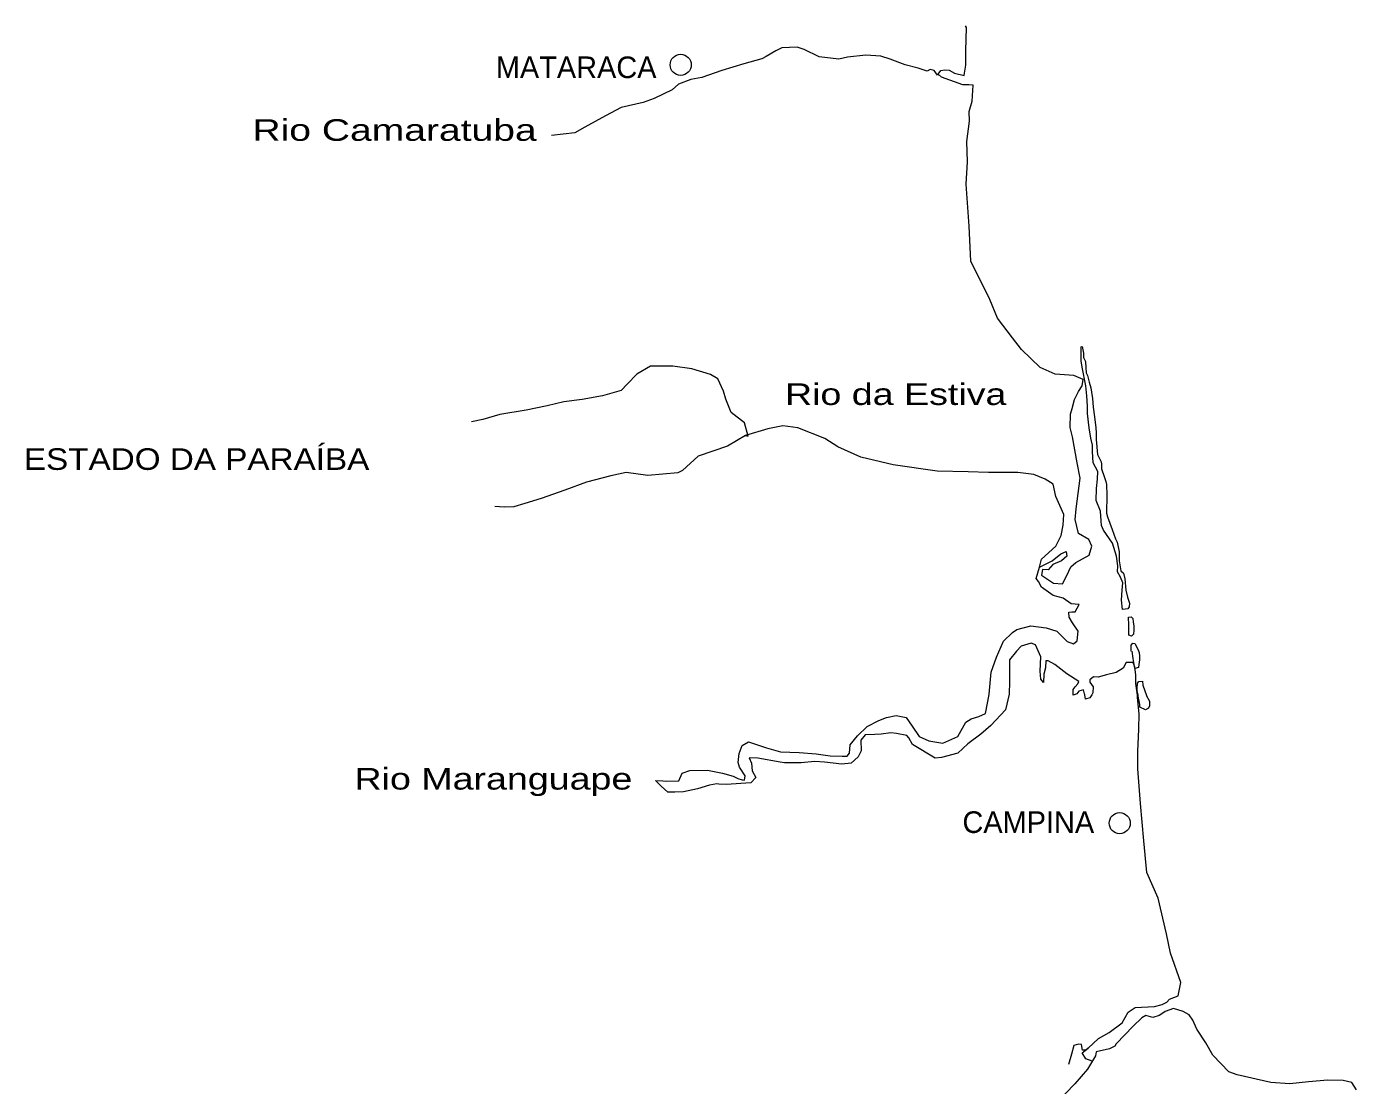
# Model space of a CAD drawing. Extents: x 47169 to 972804, y 7447977 to 9608469.
# Drawn here: x 916706 to 958528, y 9236610 to 9269921 of the extents above; entities that cross this region are included whole.
import ezdxf
from ezdxf.enums import TextEntityAlignment as Align

# ---------------------------------------------------------------- set-up
doc = ezdxf.new("R2010")
doc.units = 0
doc.header["$LTSCALE"] = 270
doc.layers.add('1', color=7, linetype='Continuous', lineweight=13)
doc.layers.add('2', color=7, linetype='Continuous', lineweight=13)
doc.layers.add('3', color=7, linetype='Continuous')

msp = doc.modelspace()

# ---------------------------------------------------------------- linework, layer by layer
at = {"layer": '1'}
for points in [[(949750.6, 9256201.2), (949604.4, 9257017), (949529.3, 9257306.9), (949536.1, 9257725.8), (949587.4, 9257901.5), (949664, 9258190.2), (949788, 9258438.5), (949902.5, 9258621.5), (949930.8, 9258821.9), (949644.8, 9258947.3), (949053.4, 9258987.6), (948577.6, 9259195.5), (947994.9, 9259760), (947713.2, 9260133.5), (947244, 9260744.7), (946997.3, 9261335.2), (946402.2, 9262542.5), (946349.1, 9263637.9), (946251.3, 9264966.3), (946294.7, 9265666.4), (946281, 9266301.5), (946356, 9266944.8), (946345.2, 9267250.7), (946446.5, 9267571.3), (946478.3, 9268077.5), (946335.4, 9268087.5), (946214.6, 9268089.6), (946151.5, 9268090.1), (945475.2, 9268332.8), (945372.9, 9268423.4), (945462.4, 9268534.6), (945575.7, 9268564.7), (945718.6, 9268554.7), (945892.9, 9268455.7), (946188.2, 9268386.8), (946205.4, 9268459.8), (946249.6, 9268707.7), (946248.8, 9269158.8), (946261.4, 9269891.2), (946229.6, 9269939.1)], [(945372.9, 9268423.4), (945356, 9268391.4), (945246.3, 9268537.4), (945126.9, 9268571.6), (945030.1, 9268517), (944743.8, 9268609.1), (944338, 9268719.9), (943869.5, 9268895.4), (943574.4, 9268988.7), (943095.9, 9269019.1), (942519.2, 9268962.8), (942253.7, 9268894), (941631.5, 9268967.7), (941163.5, 9269199.7), (940940.3, 9269275.8), (940460.2, 9269249.7), (940274.4, 9269155.9), (939968.3, 9268983.2), (939830.2, 9268904.5), (939260.5, 9268744), (938569.6, 9268536.7), (937941.8, 9268320.1), (937596.7, 9268260.8), (937210.9, 9268105.4), (937007.8, 9267931.9), (936443.9, 9267658.3), (936097.2, 9267534.7), (935407.8, 9267375.1), (934914.8, 9267108.6), (934261.6, 9266755.8), (933946.6, 9266575.5), (933218, 9266497)], [(939313.9, 9257061.5), (939401.2, 9257036.4), (939288.3, 9257456.2), (938862.1, 9257775.5), (938701.6, 9258204.5), (938618.3, 9258446.8), (938448.6, 9258836), (938210.4, 9258976.4), (937630.1, 9259152.9), (937031.5, 9259241.9), (936327.9, 9259236.5), (935900.4, 9258985), (935591, 9258667.3), (935404.4, 9258469.3), (934818.1, 9258300.1), (934175.7, 9258188.8), (933606.8, 9258116.9), (933077.3, 9257987.1), (932419.3, 9257852.7), (931594, 9257719.7), (931055.4, 9257557.8), (930702.5, 9257483)], [(948559.8, 9252911.8), (948627.3, 9253160.6), (949073.9, 9253572.5), (949239.6, 9253908), (949301, 9254236.7), (949322.6, 9254566.7), (949077, 9255141.8), (948994.8, 9255520.4), (948742.4, 9255677.6), (948384.6, 9255826.9), (947882.1, 9255890.9), (946954.8, 9255896.3), (946315.6, 9255913.8), (945339.7, 9255936.2), (943959.7, 9256132.7), (942941.2, 9256373.7), (942218.1, 9256697.7), (941807, 9256961.5), (940965.5, 9257295.2), (940494, 9257357.8), (940013.6, 9257268.6), (939313.9, 9257061.5), (938748.3, 9256715.9), (937824, 9256406.5), (937337.3, 9255955), (937191.6, 9255885.2), (936239.3, 9255802.1), (935560.9, 9255892.8), (935079.3, 9255787), (934316.6, 9255588.1), (933633.3, 9255333.2), (932885.6, 9255070), (932379.2, 9254916.7), (932033.9, 9254816.4), (931721.4, 9254805.6), (931434.7, 9254825.6)], [(946981.9, 9248922.8), (947040, 9249610.8), (947207.9, 9250083.7), (947432.6, 9250587.2), (947717.3, 9250856.3), (947846.6, 9250950.6), (948288.5, 9251065.5), (948766.6, 9251001.6), (949101.5, 9250900.2), (949431.1, 9250573.8), (949630, 9250506.8), (949743.7, 9250601.1), (949772.8, 9250899), (949601.1, 9251166.5), (949491.8, 9251345.8), (949486.5, 9251498.8), (949582.9, 9251504.6), (949687, 9251503.8), (949810.8, 9251735.5), (949555.1, 9251763.1), (949310.6, 9251935.8), (948992.2, 9252020.5), (948628.8, 9252282.8), (948527.3, 9252462.1), (948457.2, 9252559.1), (948559.8, 9252911.8), (948954.8, 9253115.8), (949230.3, 9253328.5), (949399.3, 9253406.8), (949420.3, 9253261.5), (949258.4, 9253111), (948984.9, 9252994.7), (948838.4, 9252835.2), (948654.5, 9252837.9), (948627.6, 9252661.9), (948777.3, 9252554.2), (948998.9, 9252415), (949285.7, 9252394.8), (949418.5, 9252649.7), (949550.4, 9252921.3), (949705.5, 9253056.3), (950125.2, 9253291.1), (950209.6, 9253571.9), (950117.1, 9253782.1), (949784.1, 9253972.2), (949688, 9254408.5), (949709.7, 9254754.1), (949773.5, 9255228), (949837.3, 9255709.5), (949750.6, 9256201.2)], [(949618.8, 9248900.8), (949621.2, 9249066.1), (949687.2, 9249145.3), (949769, 9249248.8), (949793.9, 9249312.9), (949422.6, 9249559.8), (949042.9, 9249855.6), (948828.8, 9249962.7), (948756.8, 9249964.4), (948746.1, 9249747.3), (948694.6, 9249547.1), (948682.5, 9249289), (948603.6, 9249394.9), (948583.5, 9249644.4), (948607.2, 9250095.3), (948437.5, 9250468), (948295.1, 9250525.7), (947989.7, 9250434), (947835.4, 9250266.9), (947614.9, 9249997.2), (947619.1, 9249304.5), (947612.6, 9248926.6), (947610.4, 9248917.6)], [(951440.5, 9250271), (951444.3, 9250456.1), (951493.6, 9250518.9), (951556.7, 9250510.6), (951658.2, 9250331.3), (951696.1, 9250226.8), (951710.7, 9250113.6), (951708.6, 9250001.7), (951681.9, 9249856.7), (951672.2, 9249752.6), (951560, 9249721.4), (951509.5, 9250036.6), (951480.4, 9250269.6)], [(951638.4, 9248883.8), (951591.5, 9249254.6), (951588.3, 9249528.3), (951560.4, 9249770.2), (951507.3, 9249915.8), (951291.3, 9249918.8), (951192.3, 9249735.6), (950974, 9249601.1), (950668.7, 9249526.1), (950403.3, 9249457.4), (950259.3, 9249459.7), (950146.7, 9249372), (950144.9, 9249292.2), (950246.7, 9249145.1), (950243, 9248960), (950203.5, 9248895.8)], [(951659.8, 9248883.6), (951636.1, 9249020.3), (951629.1, 9249109.1), (951648.1, 9249261.8), (951688.4, 9249316.9), (951800.5, 9249331.5), (951807.1, 9249202.9), (951922.1, 9248881.4)], [(938706.9, 9246080.3), (938475.5, 9246091.1), (938411.3, 9246092.7), (938187.2, 9246054.7), (937809.7, 9245940.3), (937360.3, 9245849.8), (937087.8, 9245837.6), (936872.9, 9245840.5), (936667.2, 9246020.6), (936487, 9246200.5), (936710.8, 9246197.5), (936845.8, 9246179.8), (937222.4, 9246190), (937321.9, 9246429.7), (937562.9, 9246515.2), (938122.4, 9246522.8), (938592.4, 9246435.9), (938927.2, 9246334.5), (939069.6, 9246267.9), (939205.5, 9246225.8), (939285.1, 9246208.5), (939302.9, 9246352.5), (939131.2, 9246620.9), (939085.9, 9246774.2), (939114.8, 9247055.5), (939206.6, 9247304), (939409.2, 9247420.9), (939973.6, 9247227.9), (940411.3, 9247109.1), (941001.5, 9247084.3), (941537.3, 9247044.4), (941975.5, 9246982), (942358.6, 9246967.8), (942510.4, 9246965.4), (942584.3, 9247061.2), (942605.3, 9247327), (942841.3, 9247604.3), (943141.8, 9247905.5), (943513.4, 9248094.1), (943754.5, 9248186.3), (944050.8, 9248247), (944370.5, 9248185.6), (944557.7, 9247917), (944775.4, 9247584.9), (945085.5, 9247451.6), (945523.6, 9247372.6), (945990.7, 9247590.3), (946245.8, 9248037), (946408.5, 9248147.6), (946649.5, 9248216.5), (946858.5, 9248310.1), (946981, 9248912), (946981.9, 9248922.8)], [(947610.4, 9248917.6), (947492.1, 9248430.1), (947028.2, 9247929.7), (946720.2, 9247660.7), (946306.6, 9247352.8), (945989.6, 9247059.5), (945475.5, 9246921.9), (945275.9, 9246901.4), (944563.9, 9247338.5), (944447.1, 9247541.1), (944392.4, 9247622.5), (944066.1, 9247682.8), (943890.1, 9247702), (943577.3, 9247658.1), (943385.7, 9247653), (943074.3, 9247641.2), (942943.3, 9247474.9), (942953.8, 9247136.8), (942854.7, 9246944.8), (942642.6, 9246747.1), (942346.6, 9246718.5), (941796.6, 9246782.9), (941500.9, 9246795.3), (941060.9, 9246761.3), (940541.3, 9246753.4), (940405.2, 9246778.9), (939704, 9246909.9), (939432.7, 9246914.3), (939501.1, 9246752), (939529, 9246502.4), (939638, 9246292.1), (939482.7, 9246132.7), (938706.9, 9246080.3)], [(949652.2, 9248900.5), (949618.6, 9248888.8), (949618.8, 9248900.8)], [(949983.9, 9248897.7), (949979, 9248924.6), (949949, 9249053.4), (949796.9, 9249015.9), (949730.8, 9248927.8), (949652.2, 9248900.5)], [(950217.1, 9237371.3), (950015.9, 9237449.1), (949906.8, 9237636.2), (950092.9, 9237777.6), (950417.9, 9238087.3), (950748.5, 9238275.1), (951162.1, 9238583.1), (951351, 9238918.4), (951569.3, 9239059.5), (952177.7, 9239090.8), (952418.7, 9239159.7), (952564.4, 9239229.4), (952653.8, 9239325.1), (952927.3, 9239433.6), (953006.1, 9239843), (952678.3, 9240765.7), (952560.6, 9241378.5), (952292.1, 9242501.3), (951937.9, 9243311.1), (951843.2, 9244301.7), (951735.8, 9245478.5), (951649.8, 9246574.2), (951658.8, 9247112.8), (951686.8, 9247813), (951695.4, 9248303.9), (951647.6, 9248810.8), (951638.4, 9248883.8)], [(950203.5, 9248895.8), (950145.2, 9248801.2), (950008.6, 9248762.5), (949983.9, 9248897.7)], [(951714.9, 9248512.1), (951715.9, 9248579.3), (951705.7, 9248659), (951679.4, 9248770.6), (951659.8, 9248883.6)], [(951922.1, 9248881.4), (951928.3, 9248863.8), (952022.3, 9248701.2), (952019.9, 9248548.3), (951986, 9248476.6), (951896.9, 9248420.8), (951714.9, 9248512.1)], [(958527.8, 9236469.1), (958388.1, 9236704.2), (958109.5, 9236765.4), (957629.9, 9236771.8), (957021.3, 9236725), (956437, 9236661.3), (955838.1, 9236703.1), (954779, 9236943.8), (954517.3, 9237035.9), (954014.5, 9237558.9), (953788.5, 9237948.8), (953508.6, 9238379), (953385.9, 9238662.7), (953268.8, 9238833.2), (953078, 9238932.4), (952776.4, 9239025.9), (952511, 9238940.6), (952438.5, 9238885.8), (952324.9, 9238814.7), (952123.8, 9238745.5), (951909.5, 9238812.7), (951780.3, 9238734.1), (951512.2, 9238472.6), (950974.7, 9237917.5), (950925.4, 9237845.8), (950764, 9237759.7), (950346.8, 9237670.1), (950321.3, 9237540.7), (950066.3, 9237126.1), (949674.7, 9236657.3), (949097, 9236062.7)], [(950092.9, 9237777.6), (950020.5, 9237722.8), (949908.6, 9237716), (949886.8, 9237893.5), (949791.7, 9237910.9), (949638.5, 9237865.7), (949570.8, 9237592.5), (949477.2, 9237264.1)]]:
    msp.add_lwpolyline(points, dxfattribs=at)
for points in [[(950949.4, 9253801.8), (951002.9, 9253704.9), (951062.3, 9253398.5), (951065.5, 9253117), (951123.8, 9252794), (951202.9, 9252720.2), (951248, 9252550.2), (951281.6, 9252188.6), (951334, 9251969.8), (951386.7, 9251776.6), (951384.6, 9251663.5), (951335.4, 9251607.4), (951175.6, 9251577.7), (951140.5, 9251876.2), (951161.9, 9252189.6), (951181.6, 9252423.3), (951104.4, 9252601.3), (951019.4, 9252762.7), (951023.2, 9252956.6), (950988, 9253255.1), (950858.5, 9253667.3), (950578.3, 9254073.1), (950516.4, 9254226.5), (950503.2, 9254371.8), (950483.6, 9254677.9), (950345.6, 9255010.4), (950352.1, 9255388.3), (950388.9, 9255685), (950400.9, 9255926.5), (950253.6, 9256194.8), (950227.7, 9256548.6), (950231.6, 9256750.2), (950171.3, 9256968), (950120.9, 9257298.7), (950072.6, 9257750.1), (950067.8, 9257982.9), (950049.5, 9258305.6), (950014.4, 9258619.5), (949905.1, 9259201.1), (949868, 9259402), (949870.4, 9259563.8), (949874.1, 9259740), (949876.1, 9259845.3), (949908.3, 9259860.5), (949944.3, 9259650.8), (949949.7, 9259505.6), (950004.1, 9259384.3), (950016.9, 9259183.6), (950030, 9259029.4), (950075.8, 9258940.4), (950120.6, 9258730.6), (950173.4, 9258552.8), (950195.6, 9258424), (950231.6, 9258222), (950251.5, 9257948.1), (950294.4, 9257641.9), (950328.1, 9257295.8), (950342.3, 9257142.8), (950338.4, 9256933.3), (950386.5, 9256457.5), (950471.5, 9256287.2), (950502.1, 9256230.4), (950509.2, 9256158.3), (950506.8, 9256005.4), (950590.1, 9255763.1), (950652, 9255609.6), (950665.6, 9255512), (950676.2, 9255182.8), (950667, 9254611), (950697, 9254497.7), (950850, 9254101.8)], [(951375.9, 9251148.3), (951362.6, 9251278), (951363.1, 9251342.3), (951443, 9251349.4), (951497.9, 9251300.2), (951504.8, 9251194.8), (951525.8, 9251058.3), (951523.6, 9250928.7), (951521.5, 9250809), (951456.7, 9250745.3), (951369.5, 9250778.1), (951371.6, 9250898.9)]]:
    msp.add_lwpolyline(points, close=True, dxfattribs=at)
at = {"layer": '2'}
for centre, radius in [((937276.7, 9268716.6), 331.9), ((951084.7, 9244860), 331.8)]:
    msp.add_circle(centre, radius, dxfattribs=at)

# ---------------------------------------------------------------- texts
at = {"layer": '3'}
msp.add_text('MATARACA', height=680.1, dxfattribs=at).set_placement((931463.6, 9268300.2))
for s, height, width, p in [('Rio Camaratuba', 680, 1.35, (923808.4, 9266326.8)), ('Rio da Estiva', 680.1, 1.3, (940555.6, 9258016.2)), ('ESTADO DA PARAÍBA', 679.9, 1.15, (916620.6, 9255974.4))]:
    msp.add_text(s, height=height, dxfattribs=dict(at, width=width)).set_placement(p)
at = {"layer": '3', "width": 1.3}
msp.add_text('Rio Maranguape', height=679.8, dxfattribs=at).set_placement((935755.7, 9245917.4), align=Align.RIGHT)
at = {"layer": '3'}
msp.add_text('CAMPINA', height=679.9, dxfattribs=at).set_placement((950281.4, 9244552.7), align=Align.RIGHT)

doc.saveas('drawing.dxf')
